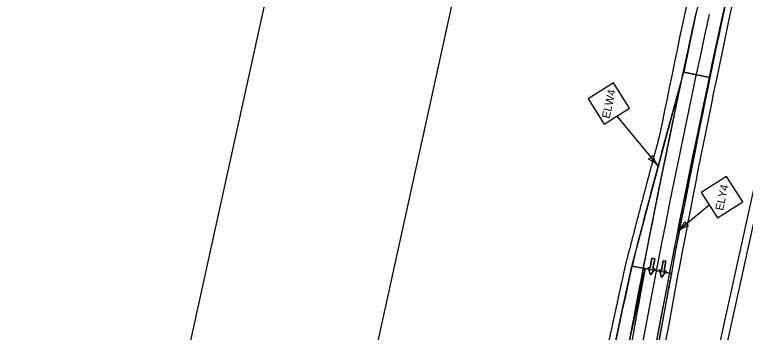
# Model space of a CAD drawing. Extents: x 14104283 to 14129344, y 8637090 to 8673339.
# Drawn here: x 14107490 to 14108148, y 8640609 to 8640895 of the extents above; entities that cross this region are included whole.
import ezdxf

# ---------------------------------------------------------------- set-up
doc = ezdxf.new("R2010")
doc.units = 0
for name, color, linetype in [('Cell', 7, 'Continuous'), ('Default', 7, 'Continuous'), ('dsnNonPlotable', 7, 'Continuous'), ('dsnPaintPlaceBrokenLineWhite', 7, 'Continuous'), ('dsnPaintPlaceEdgeLineLeftYellow', 7, 'Continuous'), ('dsnPaintPlaceEdgeLineRightWhite', 7, 'Continuous'), ('dsnStdLabel', 7, 'Continuous'), ('dsnStgShadingPrevPav', 7, 'Continuous')]:
    doc.layers.add(name, color=color, linetype=linetype)

msp = doc.modelspace()

# ---------------------------------------------------------------- linework, layer by layer
at = {"layer": 'Cell'}
for points in [[(14108063.89, 8640675.97), (14108066.35, 8640675.52), (14108064.79, 8640666.91), (14108066.63, 8640666.58), (14108062.44, 8640660.99), (14108060.48, 8640667.69), (14108062.33, 8640667.36)], [(14108073.94, 8640673.72), (14108076.4, 8640673.27), (14108074.84, 8640664.66), (14108076.68, 8640664.33), (14108072.49, 8640658.74), (14108070.53, 8640665.45), (14108072.38, 8640665.11)]]:
    msp.add_lwpolyline(points, close=True, dxfattribs=at)
for points in [[(14108062.33, 8640667.36), (14108060.48, 8640667.69), (14108062.44, 8640660.99), (14108066.63, 8640666.58), (14108064.79, 8640666.91), (14108066.35, 8640675.52), (14108063.89, 8640675.97), (14108062.33, 8640667.36)], [(14108072.38, 8640665.11), (14108070.53, 8640665.45), (14108072.49, 8640658.74), (14108076.68, 8640664.33), (14108074.84, 8640664.66), (14108076.4, 8640673.27), (14108073.94, 8640673.72), (14108072.38, 8640665.11)]]:
    msp.add_lwpolyline(points, dxfattribs=at)
at = {"layer": 'Default'}
for p, q in [((14108126.97, 8640892.05), (14108140.85, 8640955.25)), ((14108178.07, 8640812.51), (14108054.09, 8640248.16))]:
    msp.add_line(p, q, dxfattribs=at)
for centre, radius, start, end in [((14117394.14, 8638857.08), 9512, 167.610212, 171.325989), ((14117394.14, 8638857.08), 9500, 167.610212, 171.325989), ((14117394, 8638856.29), 9512, 167.610212, 169.436329), ((14117394, 8638856.29), 9488, 167.610212, 171.325989), ((14117502.5, 8638839.63), 9621.75, 168.048489, 169.460498), ((14117245.13, 8638308.71), 9497.18, 164.591267, 165.609485), ((14117342.69, 8638609.63), 9522.13, 167.509575, 168.915877)]:
    msp.add_arc(centre, radius, start, end, dxfattribs=at)
at = {"layer": 'dsnNonPlotable'}
for points in [[(14107490.45, 8639880.3), (14107826.84, 8641411.28), (14108813.31, 8641194.53), (14108476.92, 8639663.55)], [(14107651.31, 8639844.94), (14107987.7, 8641375.92), (14108480.93, 8641267.54), (14108144.54, 8639736.56)]]:
    msp.add_lwpolyline(points, close=True, dxfattribs=at)
at = {"layer": 'dsnPaintPlaceBrokenLineWhite'}
msp.add_arc((14117394.14, 8638857.08), 9500, 167.610212, 171.325989, dxfattribs=at)
at = {"layer": 'dsnPaintPlaceEdgeLineLeftYellow'}
msp.add_arc((14117586.46, 8638823.84), 9683.13, 167.279441, 171.3032, dxfattribs=at)
at = {"layer": 'dsnPaintPlaceEdgeLineRightWhite'}
for centre, radius, start, end in [((14117394.14, 8638857.08), 9512, 167.610212, 168.003119), ((14117245.13, 8638308.71), 9497.18, 164.578206, 165.609485), ((14117342.69, 8638609.63), 9522.13, 167.509575, 168.915877)]:
    msp.add_arc(centre, radius, start, end, dxfattribs=at)
at = {"layer": 'dsnStdLabel'}
for p, q in [((14108032.33, 8640803.95), (14108069.66, 8640758.72)), ((14108115.47, 8640723.79), (14108086.85, 8640700.1))]:
    msp.add_line(p, q, dxfattribs=at)
for points in [[(14108020.96, 8640796.67), (14108043.71, 8640811.22), (14108029.16, 8640833.97), (14108006.41, 8640819.42)], [(14108122.75, 8640712.41), (14108145.49, 8640726.96), (14108130.94, 8640749.71), (14108108.2, 8640735.16)]]:
    msp.add_lwpolyline(points, close=True, dxfattribs=at)
for centre, radius, start, end in [((14108057.18, 8640773.32), 8.86, 292.83851, 328.30696), ((14108087.12, 8640773.64), 22.95, 192.50153, 220.57284), ((14108052.26, 8640743.78), 22.95, 40.57268, 68.64395), ((14108072.21, 8640717.78), 22.95, 309.60838, 337.67964), ((14108101.67, 8640712.36), 8.86, 201.8742, 237.34265), ((14108101.48, 8640682.41), 22.95, 101.53722, 129.60853)]:
    msp.add_arc(centre, radius, start, end, dxfattribs=at)
at = {"layer": 'dsnStgShadingPrevPav'}
for p, q in [((14108092.51, 8640843.67), (14108116.01, 8640838.82)), ((14108116.01, 8640838.82), (14108092.51, 8640843.67)), ((14108045.92, 8640669.04), (14108057.72, 8640666.84)), ((14108081.31, 8640662.43), (14108045.92, 8640669.04)), ((14108057.72, 8640666.84), (14108081.31, 8640662.43))]:
    msp.add_line(p, q, dxfattribs=at)
msp.add_lwpolyline([(14108081.5, 8640400.87), (14108123.34, 8640591.33), (14108126.55, 8640605.98), (14108216.67, 8641016.2), (14108268.16, 8641250.61), (14108382.95, 8641773.15), (14108422.02, 8641764.57), (14108309.38, 8641251.8), (14108270.22, 8641073.55), (14108265.93, 8641054.01), (14108255.74, 8641007.62), (14108202.1, 8640763.44), (14108120.56, 8640392.29)], close=True, dxfattribs=at)
for radius, start, end in [(9522, 167.610212, 168.688952), (9512, 167.610212, 168.328257), (9512, 167.610212, 168.328257), (9488, 167.610212, 172.222077), (9482, 167.610212, 172.222077), (9488, 167.610212, 168.328257), (9488, 168.328257, 169.413861), (9512, 169.413861, 172.222077), (9512, 169.413861, 170.574102), (9488, 169.413861, 172.222077)]:
    msp.add_arc((14117407.82, 8638919.35), radius, start, end, dxfattribs=at)
for points, degree in [([(14108045.92, 8640669.04), (14108046.67, 8640671.96), (14108048.17, 8640677.8), (14108050.43, 8640686.55), (14108052.7, 8640695.31), (14108054.98, 8640704.06), (14108057.26, 8640712.8), (14108059.55, 8640721.55), (14108061.85, 8640730.29), (14108064.16, 8640739.03), (14108066.48, 8640747.76), (14108068.81, 8640756.5), (14108071.14, 8640765.23), (14108073.48, 8640773.95), (14108075.83, 8640782.68), (14108078.19, 8640791.4), (14108080.55, 8640800.12), (14108082.93, 8640808.84), (14108085.31, 8640817.55), (14108087.7, 8640826.26), (14108090.1, 8640834.97), (14108091.7, 8640840.77), (14108092.51, 8640843.67)], 3), ([(14108045.92, 8640669.04), (14108046.67, 8640671.96), (14108048.17, 8640677.8), (14108050.43, 8640686.55), (14108052.7, 8640695.31), (14108054.98, 8640704.06), (14108057.26, 8640712.8), (14108059.55, 8640721.55), (14108061.85, 8640730.29), (14108064.16, 8640739.03), (14108066.48, 8640747.76), (14108068.81, 8640756.5), (14108071.14, 8640765.23), (14108073.48, 8640773.95), (14108075.83, 8640782.68), (14108078.19, 8640791.4), (14108080.55, 8640800.12), (14108082.93, 8640808.84), (14108085.31, 8640817.55), (14108087.7, 8640826.26), (14108090.1, 8640834.97), (14108091.7, 8640840.77), (14108092.51, 8640843.67)], 3), ([(14108070.77, 8640786.95), (14108070.25, 8640785.01), (14108069.2, 8640781.13), (14108067.63, 8640775.31), (14108066.07, 8640769.49), (14108064.51, 8640763.67), (14108062.96, 8640757.84), (14108061.41, 8640752.02), (14108059.86, 8640746.19), (14108058.31, 8640740.36), (14108056.77, 8640734.54), (14108055.23, 8640728.71), (14108053.7, 8640722.87), (14108052.17, 8640717.04), (14108050.64, 8640711.21), (14108049.12, 8640705.37), (14108047.6, 8640699.54), (14108046.09, 8640693.7), (14108044.58, 8640687.86), (14108043.07, 8640682.02), (14108041.56, 8640676.18), (14108040.56, 8640672.28), (14108040.06, 8640670.34)], 3), ([(14108040.07, 8640670.33), (14108039.11, 8640666.01), (14108035.79, 8640651.03), (14108029.85, 8640623.7), (14108025.19, 8640602.04), (14108020.26, 8640578.84), (14108015.47, 8640556.04), (14108010.72, 8640533.12), (14108006.03, 8640510.22), (14108001.39, 8640487.29), (14107996.81, 8640464.36), (14107992.28, 8640441.41), (14107987.82, 8640418.46), (14107983.4, 8640395.49), (14107979.05, 8640372.51), (14107974.75, 8640349.53), (14107970.51, 8640326.51), (14107966.33, 8640303.59), (14107962.15, 8640280.24), (14107958.29, 8640258.43), (14107953.48, 8640230.88), (14107950.9, 8640215.75), (14107950.15, 8640211.39)], 2), ([(14107956.07, 8640210.37), (14107957.38, 8640218.06), (14107960.02, 8640233.43), (14107964.04, 8640256.47), (14107968.11, 8640279.5), (14107972.24, 8640302.51), (14107976.42, 8640325.52), (14107980.66, 8640348.51), (14107984.96, 8640371.49), (14107989.32, 8640394.46), (14107993.73, 8640417.41), (14107998.19, 8640440.35), (14108002.71, 8640463.28), (14108007.29, 8640486.2), (14108011.92, 8640509.1), (14108016.61, 8640531.99), (14108021.36, 8640554.87), (14108026.16, 8640577.73), (14108031.01, 8640600.58), (14108035.93, 8640623.41), (14108040.89, 8640646.24), (14108044.25, 8640661.44), (14108045.92, 8640669.04)], 3), ([(14108043.91, 8640659.92), (14108044.16, 8640661.06), (14108044.41, 8640662.2), (14108044.67, 8640663.34)], 2), ([(14108044.67, 8640663.34), (14108044.75, 8640663.72), (14108044.83, 8640664.1), (14108044.92, 8640664.48)], 2), ([(14108044.92, 8640664.48), (14108045, 8640664.86), (14108045.09, 8640665.24), (14108045.17, 8640665.62)], 2), ([(14108045.17, 8640665.62), (14108045.34, 8640666.38), (14108045.5, 8640667.14), (14108045.67, 8640667.9)], 2), ([(14108045.67, 8640667.9), (14108045.76, 8640668.28), (14108045.84, 8640668.66), (14108045.92, 8640669.04)], 2), ([(14108056.97, 8640663.42), (14108056.88, 8640663.04), (14108056.8, 8640662.66), (14108056.71, 8640662.28)], 2), ([(14108056.71, 8640662.28), (14108056.8, 8640662.66), (14108056.88, 8640663.04), (14108056.97, 8640663.42)], 2), ([(14108057.22, 8640664.56), (14108057.13, 8640664.18), (14108057.05, 8640663.8), (14108056.97, 8640663.42)], 2), ([(14108056.97, 8640663.42), (14108057.05, 8640663.8), (14108057.13, 8640664.18), (14108057.22, 8640664.56)], 2), ([(14108057.47, 8640665.7), (14108057.38, 8640665.32), (14108057.3, 8640664.94), (14108057.22, 8640664.56)], 2), ([(14108057.22, 8640664.56), (14108057.3, 8640664.94), (14108057.38, 8640665.32), (14108057.47, 8640665.7)], 2), ([(14108057.72, 8640666.84), (14108057.64, 8640666.46), (14108057.55, 8640666.08), (14108057.47, 8640665.7)], 2), ([(14108057.47, 8640665.7), (14108057.55, 8640666.08), (14108057.64, 8640666.46), (14108057.72, 8640666.84)], 2), ([(14108042.91, 8640655.36), (14108043.07, 8640656.12), (14108043.24, 8640656.88), (14108043.41, 8640657.64)], 2), ([(14108043.41, 8640657.64), (14108043.49, 8640658.02), (14108043.58, 8640658.4), (14108043.66, 8640658.78)], 2), ([(14108043.66, 8640658.78), (14108043.74, 8640659.16), (14108043.83, 8640659.54), (14108043.91, 8640659.92)], 2), ([(14108055.71, 8640657.73), (14108055.21, 8640655.45), (14108054.7, 8640653.17), (14108054.2, 8640650.89)], 2), ([(14108054.2, 8640650.89), (14108054.7, 8640653.17), (14108055.21, 8640655.45), (14108055.71, 8640657.73)], 2), ([(14108055.96, 8640658.87), (14108055.88, 8640658.49), (14108055.79, 8640658.11), (14108055.71, 8640657.73)], 2), ([(14108055.71, 8640657.73), (14108055.79, 8640658.11), (14108055.88, 8640658.49), (14108055.96, 8640658.87)], 2), ([(14108056.71, 8640662.28), (14108056.46, 8640661.14), (14108056.21, 8640660), (14108055.96, 8640658.87)], 2), ([(14108055.96, 8640658.87), (14108056.21, 8640660), (14108056.46, 8640661.14), (14108056.71, 8640662.28)], 2), ([(14108041.65, 8640649.66), (14108041.74, 8640650.04), (14108041.82, 8640650.42), (14108041.9, 8640650.8)], 2), ([(14108041.9, 8640650.8), (14108041.99, 8640651.18), (14108042.07, 8640651.56), (14108042.15, 8640651.94)], 2), ([(14108042.15, 8640651.94), (14108042.4, 8640653.08), (14108042.65, 8640654.22), (14108042.91, 8640655.36)], 2), ([(14108053.95, 8640649.75), (14108053.87, 8640649.37), (14108053.79, 8640648.99), (14108053.7, 8640648.62)], 2), ([(14108053.7, 8640648.62), (14108053.79, 8640648.99), (14108053.87, 8640649.37), (14108053.95, 8640649.75)], 2), ([(14108054.2, 8640650.89), (14108054.12, 8640650.51), (14108054.04, 8640650.13), (14108053.95, 8640649.75)], 2), ([(14108053.95, 8640649.75), (14108054.04, 8640650.13), (14108054.12, 8640650.51), (14108054.2, 8640650.89)], 2), ([(14108039.9, 8640641.67), (14108040.15, 8640642.81), (14108040.4, 8640643.95), (14108040.65, 8640645.09)], 2), ([(14108040.65, 8640645.09), (14108040.73, 8640645.47), (14108040.82, 8640645.85), (14108040.9, 8640646.23)], 2), ([(14108040.9, 8640646.23), (14108040.98, 8640646.61), (14108041.07, 8640646.99), (14108041.15, 8640647.37)], 2), ([(14108041.15, 8640647.37), (14108041.23, 8640647.76), (14108041.32, 8640648.14), (14108041.4, 8640648.52)], 2), ([(14108041.4, 8640648.52), (14108041.48, 8640648.9), (14108041.57, 8640649.28), (14108041.65, 8640649.66)], 2), ([(14108052.7, 8640644.06), (14108052.45, 8640642.92), (14108052.2, 8640641.78), (14108051.95, 8640640.64)], 2), ([(14108051.95, 8640640.64), (14108052.2, 8640641.78), (14108052.45, 8640642.92), (14108052.7, 8640644.06)], 2), ([(14108052.95, 8640645.2), (14108052.87, 8640644.82), (14108052.79, 8640644.44), (14108052.7, 8640644.06)], 2), ([(14108052.7, 8640644.06), (14108052.79, 8640644.44), (14108052.87, 8640644.82), (14108052.95, 8640645.2)], 2), ([(14108053.45, 8640647.48), (14108053.29, 8640646.72), (14108053.12, 8640645.96), (14108052.95, 8640645.2)], 2), ([(14108052.95, 8640645.2), (14108053.12, 8640645.96), (14108053.29, 8640646.72), (14108053.45, 8640647.48)], 2), ([(14108053.7, 8640648.62), (14108053.62, 8640648.24), (14108053.54, 8640647.86), (14108053.45, 8640647.48)], 2), ([(14108053.45, 8640647.48), (14108053.54, 8640647.86), (14108053.62, 8640648.24), (14108053.7, 8640648.62)], 2), ([(14108038.66, 8640635.97), (14108038.74, 8640636.35), (14108038.82, 8640636.73), (14108038.91, 8640637.11)], 2), ([(14108038.91, 8640637.11), (14108038.99, 8640637.49), (14108039.07, 8640637.87), (14108039.16, 8640638.25)], 2), ([(14108039.16, 8640638.25), (14108039.4, 8640639.39), (14108039.65, 8640640.53), (14108039.9, 8640641.67)], 2), ([(14108051.46, 8640638.36), (14108051.04, 8640636.46), (14108050.63, 8640634.56), (14108050.21, 8640632.66)], 2), ([(14108050.21, 8640632.66), (14108050.63, 8640634.56), (14108051.04, 8640636.46), (14108051.46, 8640638.36)], 2), ([(14108051.7, 8640639.5), (14108051.62, 8640639.12), (14108051.54, 8640638.74), (14108051.46, 8640638.36)], 2), ([(14108051.46, 8640638.36), (14108051.54, 8640638.74), (14108051.62, 8640639.12), (14108051.7, 8640639.5)], 2), ([(14108051.95, 8640640.64), (14108051.87, 8640640.26), (14108051.79, 8640639.88), (14108051.7, 8640639.5)], 2), ([(14108051.7, 8640639.5), (14108051.79, 8640639.88), (14108051.87, 8640640.26), (14108051.95, 8640640.64)], 2), ([(14108037.17, 8640629.12), (14108037.25, 8640629.5), (14108037.34, 8640629.88), (14108037.42, 8640630.26)], 2), ([(14108037.42, 8640630.26), (14108037.75, 8640631.78), (14108038.08, 8640633.3), (14108038.41, 8640634.83)], 2), ([(14108038.41, 8640634.83), (14108038.49, 8640635.21), (14108038.58, 8640635.59), (14108038.66, 8640635.97)], 2), ([(14108049.97, 8640631.52), (14108049.22, 8640628.11), (14108048.48, 8640624.69), (14108047.74, 8640621.27)], 2), ([(14108047.74, 8640621.27), (14108048.48, 8640624.69), (14108049.22, 8640628.11), (14108049.97, 8640631.52)], 2), ([(14108050.21, 8640632.66), (14108050.13, 8640632.28), (14108050.05, 8640631.9), (14108049.97, 8640631.52)], 2), ([(14108049.97, 8640631.52), (14108050.05, 8640631.9), (14108050.13, 8640632.28), (14108050.21, 8640632.66)], 2), ([(14108035.93, 8640623.41), (14108036.02, 8640623.79), (14108036.1, 8640624.17), (14108036.18, 8640624.55)], 2), ([(14108036.18, 8640624.55), (14108036.26, 8640624.93), (14108036.35, 8640625.32), (14108036.43, 8640625.7)], 2), ([(14108036.43, 8640625.7), (14108036.51, 8640626.08), (14108036.59, 8640626.46), (14108036.68, 8640626.84)], 2), ([(14108036.68, 8640626.84), (14108036.84, 8640627.6), (14108037.01, 8640628.36), (14108037.17, 8640629.12)], 2), ([(14108034.45, 8640616.56), (14108034.7, 8640617.71), (14108034.95, 8640618.85), (14108035.19, 8640619.99)], 2), ([(14108035.19, 8640619.99), (14108035.44, 8640621.13), (14108035.69, 8640622.27), (14108035.93, 8640623.41)], 2), ([(14108047, 8640617.85), (14108046.92, 8640617.47), (14108046.84, 8640617.09), (14108046.75, 8640616.71)], 2), ([(14108046.75, 8640616.71), (14108046.84, 8640617.09), (14108046.92, 8640617.47), (14108047, 8640617.85)], 2), ([(14108047.25, 8640618.99), (14108047.17, 8640618.61), (14108047.08, 8640618.23), (14108047, 8640617.85)], 2), ([(14108047, 8640617.85), (14108047.08, 8640618.23), (14108047.17, 8640618.61), (14108047.25, 8640618.99)], 2), ([(14108047.49, 8640620.13), (14108047.41, 8640619.75), (14108047.33, 8640619.37), (14108047.25, 8640618.99)], 2), ([(14108047.25, 8640618.99), (14108047.33, 8640619.37), (14108047.41, 8640619.75), (14108047.49, 8640620.13)], 2), ([(14108047.74, 8640621.27), (14108047.66, 8640620.89), (14108047.58, 8640620.51), (14108047.49, 8640620.13)], 2), ([(14108047.49, 8640620.13), (14108047.58, 8640620.51), (14108047.66, 8640620.89), (14108047.74, 8640621.27)], 2), ([(14108032.98, 8640609.71), (14108033.31, 8640611.24), (14108033.63, 8640612.76), (14108033.96, 8640614.28)], 2), ([(14108033.96, 8640614.28), (14108034.04, 8640614.66), (14108034.13, 8640615.04), (14108034.21, 8640615.42)], 2), ([(14108034.21, 8640615.42), (14108034.29, 8640615.8), (14108034.37, 8640616.18), (14108034.45, 8640616.56)], 2), ([(14108045.77, 8640612.15), (14108045.61, 8640611.39), (14108045.44, 8640610.62), (14108045.28, 8640609.86)], 2), ([(14108045.28, 8640609.86), (14108045.44, 8640610.62), (14108045.61, 8640611.39), (14108045.77, 8640612.15)], 2), ([(14108046.02, 8640613.29), (14108045.93, 8640612.91), (14108045.85, 8640612.53), (14108045.77, 8640612.15)], 2), ([(14108045.77, 8640612.15), (14108045.85, 8640612.53), (14108045.93, 8640612.91), (14108046.02, 8640613.29)], 2), ([(14108046.51, 8640615.57), (14108046.34, 8640614.81), (14108046.18, 8640614.05), (14108046.02, 8640613.29)], 2), ([(14108046.02, 8640613.29), (14108046.18, 8640614.05), (14108046.34, 8640614.81), (14108046.51, 8640615.57)], 2), ([(14108046.75, 8640616.71), (14108046.67, 8640616.33), (14108046.59, 8640615.95), (14108046.51, 8640615.57)], 2), ([(14108046.51, 8640615.57), (14108046.59, 8640615.95), (14108046.67, 8640616.33), (14108046.75, 8640616.71)], 2), ([(14108032.74, 8640608.57), (14108032.82, 8640608.95), (14108032.9, 8640609.33), (14108032.98, 8640609.71)], 2), ([(14108045.28, 8640609.86), (14108045.2, 8640609.48), (14108045.12, 8640609.1), (14108045.03, 8640608.72)], 2), ([(14108045.03, 8640608.72), (14108045.12, 8640609.1), (14108045.2, 8640609.48), (14108045.28, 8640609.86)], 2)]:
    msp.add_open_spline(points, degree=degree, dxfattribs=at)

# ---------------------------------------------------------------- texts
at = {"layer": 'dsnStdLabel'}
for s, p in [('ELW4', (14108025.69, 8640801.41)), ('ELY4', (14108127.77, 8640718.51))]:
    msp.add_text(s, height=7.2, rotation=77.60784, dxfattribs=at).set_placement(p)

doc.saveas('drawing.dxf')
